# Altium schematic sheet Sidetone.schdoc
size 201 x 75 mm
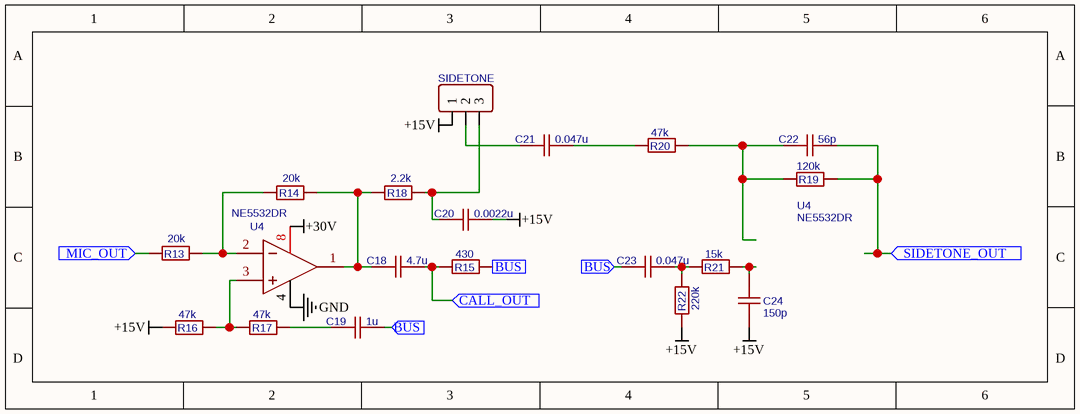
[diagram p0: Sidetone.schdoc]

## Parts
(Parts that share a designator on the sheet are numbered #1, #2 ... from top to bottom, then left to right.)
C18  4.7u  [C1206]
C19  1u  [C1206]
C20  0.0022u  [C1206]
C21  0.047u  [C0805]
C22  56p  [C0603]
C23  0.047u  [C0805]
C24  150p  [C0805]
J3  SIDETONE  [HDR-M-2.54_1X3]
R13  20k  [R0805]
R14  20k  [R0805]
R15  430  [R0805]
R16  47k  [R0805]
R17  47k  [R0805]
R18  2.2k  [R0805]
R19  120k  [R0805]
R20  47k  [R0805]
R21  15k  [R0805]
R22  220k  [R0805]
U4#1  NE5532DR  [SOIC-8_L4.9-W3.9-P1.27-LS6.0-BL]
U4#2  NE5532DR  [SOIC-8_L4.9-W3.9-P1.27-LS6.0-BL]

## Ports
BUS (in), CALL_OUT (in), MIC_OUT (in), SIDETONE_OUT (in)

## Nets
+15V: C20.2 C24.1 J3.1 R16.1 R22.1
+30V: U4#2.8(VCC+)
GND: U4#2.4(VCC-/GND)
BUS: C19.2 C23.1 R15.2 ; port BUS
CALL_OUT: C18.2 R15.1 ; port CALL_OUT
MIC_OUT: R13.1 ; port MIC_OUT
SIDETONE_OUT: C22.2 R19.2 ; port SIDETONE_OUT
NetC18_1: C18.1 R14.2 R18.1 U4#2.1(OUT1)
NetC19_1: C19.1 R17.2
NetC20_1: C20.1 J3.3 R18.2
NetC21_1: C21.1 J3.2
NetC21_2: C21.2 R20.1
NetC22_1: C22.1 R19.1 R20.2
NetC23_2: C23.2 R21.1 R22.2
NetC24_2: C24.2 R21.2
NetR13_2: R13.2 R14.1 U4#2.2(IN1-)
NetR16_2: R16.2 R17.1 U4#2.3(IN1+)

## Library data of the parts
C18 = 4.7u: BOM_Manufacturer Part: CL21A475KAQNNNE; BOM_Manufacturer: SAMSUNG(三星); nameAlias: Value(F); Contributor: LCEDA_Lib
C19 = 1u: BOM_Manufacturer Part: CL31B105KBHNNNE; BOM_Manufacturer: SAMSUNG(三星); nameAlias: Value(F); Contributor: LCEDA_Lib
C20 = 0.0022u: BOM_Manufacturer Part: CL21C222JBFNNNE; BOM_Manufacturer: SAMSUNG(三星); nameAlias: Value(F); Contributor: LCEDA_Lib
C21 C23 = 0.047u: BOM_Manufacturer Part: CL21B473KBCNNNC; BOM_Manufacturer: SAMSUNG(三星); nameAlias: Value(F); Contributor: LCEDA_Lib
C22 = 56p: BOM_Manufacturer Part: CL10C560JB8NNNC; BOM_Manufacturer: SAMSUNG(三星); nameAlias: Value(F); Contributor: LCEDA_Lib
C24 = 150p: BOM_Manufacturer Part: 0805B151K500NT; BOM_Manufacturer: FH(风华); nameAlias: Value(F); Contributor: LCEDA_Lib
J3 = SIDETONE: Contributor: LCEDA_Lib
R13 R14 = 20k: BOM_Manufacturer Part: 0805W8F2002T5E; BOM_Manufacturer: UNI-ROYAL(厚声); nameAlias: Value(Ω); Contributor: LCEDA_Lib
R15 = 430: BOM_Manufacturer Part: 0805W8F4700T5E; BOM_Manufacturer: UNI-ROYAL(厚声); nameAlias: Value(Ω); Contributor: LCEDA_Lib
R16 R17 R20 = 47k: BOM_Manufacturer Part: 0805W8F4702T5E; BOM_Manufacturer: UNI-ROYAL(厚声); nameAlias: Value(Ω); Contributor: LCEDA_Lib
R18 = 2.2k: BOM_Manufacturer Part: 0805W8F2201T5E; BOM_Manufacturer: UNI-ROYAL(厚声); nameAlias: Value(Ω); Contributor: LCEDA_Lib
R19 = 120k: BOM_Manufacturer Part: 0805W8F1203T5E; BOM_Manufacturer: UNI-ROYAL(厚声); nameAlias: Value(Ω); Contributor: LCEDA_Lib
R21 = 15k: BOM_Manufacturer Part: 0805W8F1502T5E; BOM_Manufacturer: UNI-ROYAL(厚声); nameAlias: Value(Ω); Contributor: LCEDA_Lib
R22 = 220k: BOM_Manufacturer Part: 0805W8F2203T5E; BOM_Manufacturer: UNI-ROYAL(厚声); nameAlias: Value(Ω); Contributor: LCEDA_Lib
U4#1 U4#2 = NE5532DR: BOM_Manufacturer: TI(德州仪器); subpart_no: 2; SMT Type: Basic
